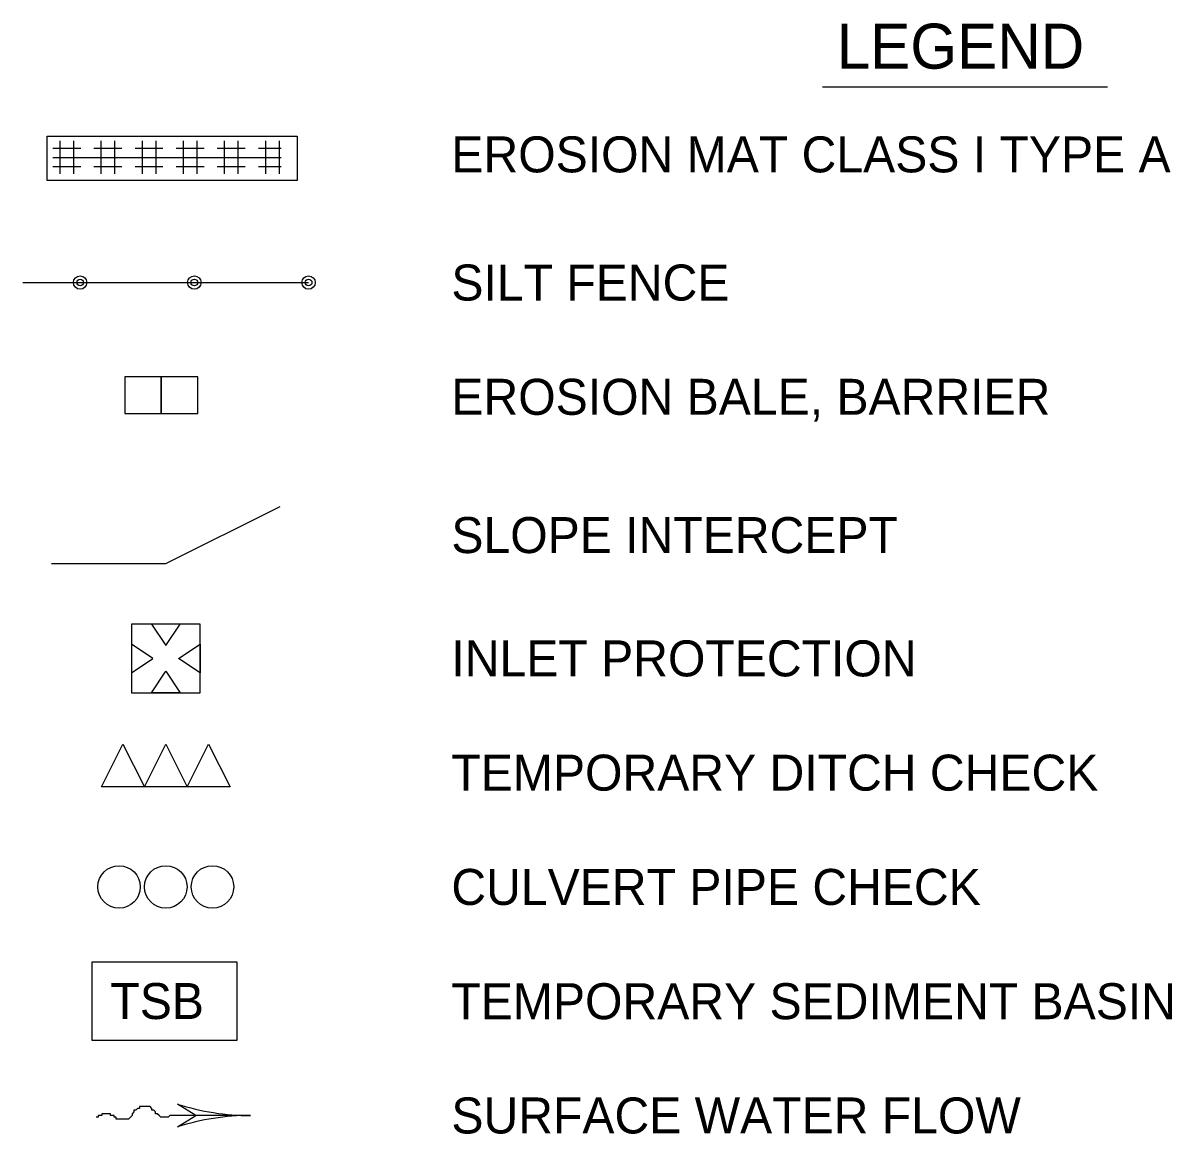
# Model space of a CAD drawing. Extents: x 358661 to 362123, y 127010 to 127205.
# Drawn here: x 361921.5 to 362122.6, y 127010.2 to 127204.6 of the extents above; entities that cross this region are included whole.
import ezdxf

# ---------------------------------------------------------------- set-up
doc = ezdxf.new("R2010")
doc.units = 0
for name, color, linetype in [('Level 51', 7, 'Continuous'), ('P_EC', 7, 'Continuous'), ('P_RW_SlopeIntercepts', 7, 'Continuous'), ('P_TC_Text', 7, 'Continuous')]:
    doc.layers.add(name, color=color, linetype=linetype)

msp = doc.modelspace()

# ---------------------------------------------------------------- linework, layer by layer
at = {"layer": 'P_EC'}
for p, q in [((361927.98, 127178.25), (361927.98, 127184.01)), ((361930.38, 127178.25), (361930.38, 127184.01)), ((361935.18, 127178.25), (361935.18, 127184.01)), ((361937.58, 127178.25), (361937.58, 127184.01)), ((361942.38, 127178.25), (361942.38, 127184.01)), ((361944.78, 127178.25), (361944.78, 127184.01)), ((361949.58, 127178.25), (361949.58, 127184.01)), ((361951.98, 127178.25), (361951.98, 127184.01)), ((361956.78, 127178.25), (361956.78, 127184.01)), ((361959.18, 127178.25), (361959.18, 127184.01)), ((361963.98, 127178.25), (361963.98, 127184.01)), ((361966.38, 127178.25), (361966.38, 127184.01)), ((361926.7, 127181.13), (361966.7, 127181.13)), ((361921.48, 127159.22), (361971.48, 127159.22)), ((361961.32, 127013.44), (361947.19, 127013.44))]:
    msp.add_line(p, q, dxfattribs=at)
for points in [[(361925.69, 127184.82), (361969.49, 127184.82), (361969.49, 127177.07), (361925.69, 127177.07)], [(361939.3, 127136.31), (361945.7, 127136.31), (361945.7, 127142.71), (361939.3, 127142.71)], [(361945.7, 127136.31), (361952.1, 127136.31), (361952.1, 127142.71), (361945.7, 127142.71)], [(361940.48, 127087.44), (361952.48, 127087.44), (361952.48, 127099.44), (361940.48, 127099.44)], [(361946.48, 127095.69), (361948.98, 127099.44), (361943.98, 127099.44)], [(361944.23, 127093.44), (361940.48, 127095.94), (361940.48, 127090.94)], [(361948.73, 127093.44), (361952.48, 127095.94), (361952.48, 127090.94)], [(361946.48, 127091.19), (361948.98, 127087.44), (361943.98, 127087.44)], [(361935.23, 127070.94), (361938.98, 127078.44), (361942.73, 127070.94)], [(361942.73, 127070.94), (361946.48, 127078.44), (361950.23, 127070.94)], [(361950.23, 127070.94), (361953.98, 127078.44), (361957.73, 127070.94)], [(361933.6, 127040.32), (361958.93, 127040.32), (361958.93, 127026.55), (361933.6, 127026.55)]]:
    msp.add_lwpolyline(points, close=True, dxfattribs=at)
for points in [[(361926.7, 127182.73), (361931.58, 127182.73)], [(361933.9, 127182.73), (361938.78, 127182.73)], [(361941.1, 127182.73), (361945.98, 127182.73)], [(361948.3, 127182.73), (361953.18, 127182.73)], [(361955.5, 127182.73), (361960.38, 127182.73)], [(361962.7, 127182.73), (361966.7, 127182.73)], [(361926.7, 127179.53), (361931.58, 127179.53)], [(361933.9, 127179.53), (361938.78, 127179.53)], [(361941.1, 127179.53), (361945.98, 127179.53)], [(361948.3, 127179.53), (361953.18, 127179.53)], [(361955.5, 127179.53), (361960.38, 127179.53)], [(361962.7, 127179.53), (361966.7, 127179.53)], [(361921.48, 127159.22), (361971.48, 127159.22)], [(361947.19, 127013.44), (361946.88, 127013.12), (361946.56, 127013.12), (361946.25, 127013.12), (361945.93, 127013.12), (361945.62, 127013.12), (361945.31, 127013.44), (361944.99, 127013.75), (361944.68, 127013.75), (361944.68, 127014.06), (361944.36, 127014.38), (361944.05, 127014.38), (361944.05, 127014.69), (361943.74, 127015.01), (361943.42, 127015.01), (361943.11, 127015.01), (361942.79, 127015.01), (361942.48, 127015.01), (361942.17, 127015.01), (361941.85, 127015.01), (361941.85, 127014.69), (361941.54, 127014.69), (361941.22, 127014.38), (361940.91, 127014.38), (361940.91, 127014.06), (361940.6, 127013.75), (361940.6, 127013.44), (361940.28, 127013.12), (361939.97, 127012.81), (361939.65, 127012.81), (361939.34, 127012.81), (361939.03, 127012.81), (361938.71, 127012.81), (361938.4, 127012.81), (361938.08, 127012.81), (361937.77, 127012.81), (361937.77, 127013.12), (361937.46, 127013.12), (361937.46, 127013.44), (361937.14, 127013.44), (361936.83, 127013.44), (361936.83, 127013.75), (361936.52, 127013.75), (361936.2, 127013.75), (361935.89, 127013.75), (361935.57, 127013.75), (361935.26, 127013.75), (361935.26, 127013.44), (361934.95, 127013.44), (361934.63, 127013.44), (361934.63, 127013.12), (361934.32, 127013.12), (361934.32, 127013.12)], [(361948.52, 127011.43), (361951.72, 127013.43), (361948.52, 127015.43)]]:
    msp.add_lwpolyline(points, dxfattribs=at)
for centre, radius in [((361931.48, 127159.22), 1.17), ((361931.48, 127159.22), 0.587), ((361951.48, 127159.22), 1.17), ((361951.48, 127159.22), 0.587), ((361971.48, 127159.22), 1.17), ((361971.48, 127159.22), 0.587), ((361938.3, 127053.44), 3.72), ((361946.48, 127053.44), 3.72), ((361954.66, 127053.44), 3.72)]:
    msp.add_circle(centre, radius, dxfattribs=at)
for centre, start, end in [((361961.32, 127055.39), 252.2377, 270), ((361961.32, 126971.48), 90, 107.7623)]:
    msp.add_arc(centre, 41.96, start, end, dxfattribs=at)
at = {"layer": 'P_RW_SlopeIntercepts'}
msp.add_lwpolyline([(361926.48, 127110.02), (361946.48, 127110.02), (361966.48, 127120.02)], dxfattribs=at)
at = {"layer": 'P_TC_Text'}
msp.add_line((362061.43, 127193.45), (362111.34, 127193.45), dxfattribs=at)

# ---------------------------------------------------------------- texts
at = {"layer": 'Level 51'}
for s, height, p in [('LEGEND', 7.88, (362063.94, 127196.65)), ('EROSION MAT CLASS I TYPE A', 6.3, (361996.48, 127178.5)), ('SILT FENCE', 6.3, (361996.48, 127156.07)), ('EROSION BALE, BARRIER', 6.3, (361996.48, 127136.07)), ('SLOPE INTERCEPT', 6.3, (361996.48, 127111.87)), ('INLET PROTECTION', 6.3, (361996.48, 127090.29)), ('TEMPORARY DITCH CHECK', 6.3, (361996.48, 127070.29)), ('CULVERT PIPE CHECK', 6.3, (361996.48, 127050.29)), ('TEMPORARY SEDIMENT BASIN', 6.3, (361996.48, 127030.29)), ('SURFACE WATER FLOW', 6.3, (361996.48, 127010.29))]:
    msp.add_text(s, height=height, rotation=360, dxfattribs=at).set_placement(p)
at = {"layer": 'P_EC'}
msp.add_text('TSB', height=6.3, rotation=360, dxfattribs=at).set_placement((361936.78, 127030.32))

doc.saveas('drawing.dxf')
